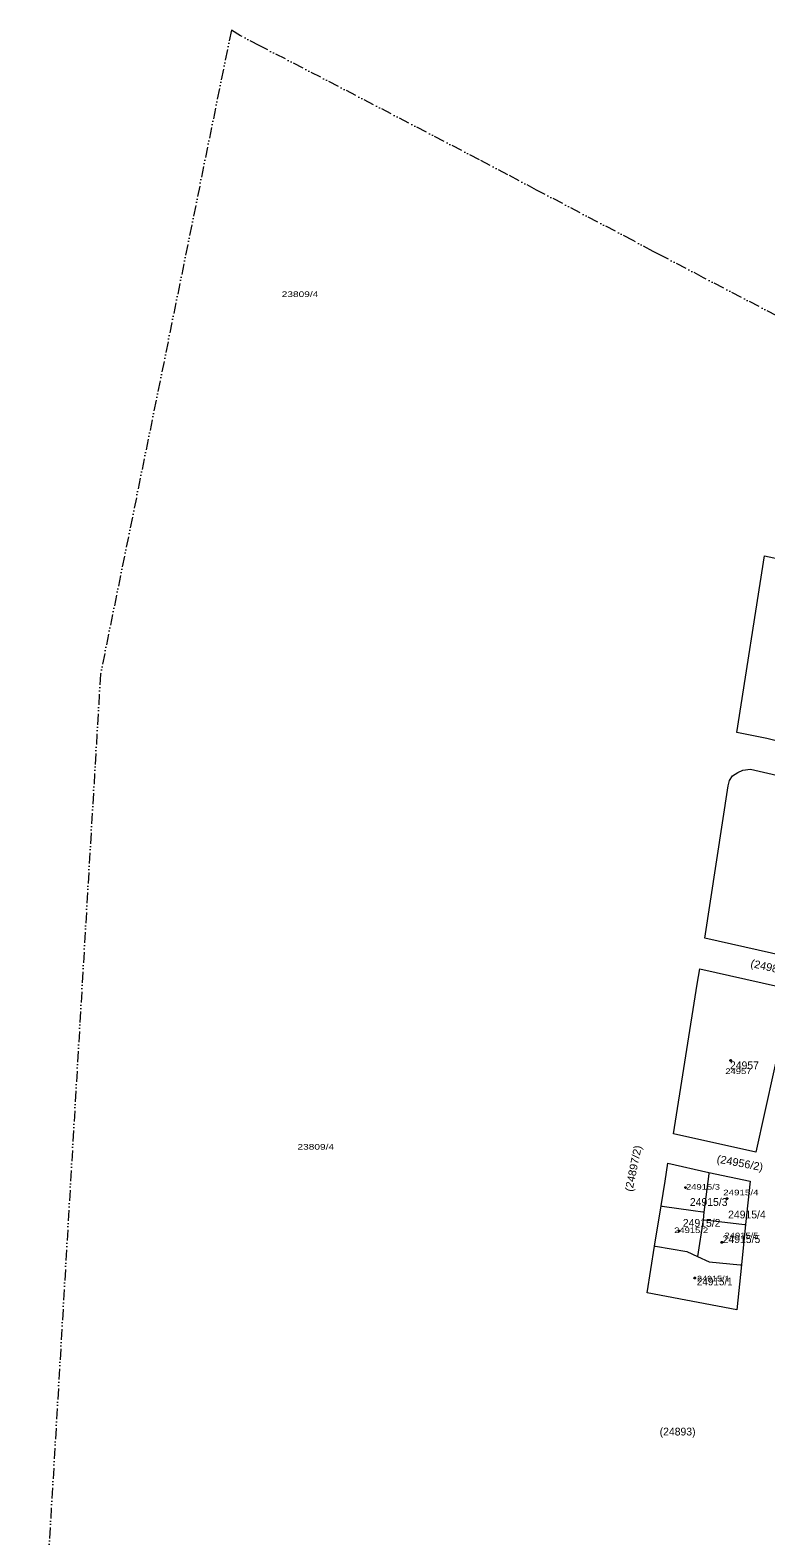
# Model space of a CAD drawing. Extents: x 649608 to 651081, y 237980 to 241202.
# Drawn here: x 649608 to 649949, y 240505 to 241202 of the extents above; entities that cross this region are included whole.
import ezdxf

# ---------------------------------------------------------------- set-up
doc = ezdxf.new("R2010")
doc.units = 0
doc.header["$PDMODE"] = 32
doc.header["$PDSIZE"] = 0.5
doc.linetypes.add('DASH_DOUBLE_DOT', pattern=[9.2, 5, -1.2, 0.3, -1.2, 0.3, -1.2])
for name, color, linetype in [('19', 7, 'Continuous'), ('20', 7, 'Continuous'), ('6', 7, 'Continuous')]:
    doc.layers.add(name, color=color, linetype=linetype)
for name, color, linetype, lineweight in [('3', 7, 'Continuous', 13), ('5', 7, 'Continuous', 13), ('52', 7, 'DASH_DOUBLE_DOT', 13)]:
    doc.layers.add(name, color=color, linetype=linetype, lineweight=lineweight)

msp = doc.modelspace()

# ---------------------------------------------------------------- linework, layer by layer
at = {"layer": '3'}
msp.add_line((649903.384, 240678.051), (649922.472, 240673.617), dxfattribs=at)
for points in [[(649984.472, 240865.644), (649949.238, 240874.49), (649935.422, 240877.247), (649948.175, 240959.032), (650002.431, 240947.466)], [(649963.751, 240772.414), (649920.651, 240782.136), (649931.296, 240852.609), (649931.915, 240855.114), (649933.387, 240857.24), (649935.862, 240858.812), (649935.887, 240858.811), (649938.131, 240859.789), (649941.756, 240860.26), (649981.062, 240851.161), (649964.785, 240776.903)], [(649918.324, 240767.869), (649960.797, 240758.3), (649944.236, 240683.1), (649906.134, 240691.619), (649917.099, 240760.848)]]:
    msp.add_lwpolyline(points, close=True, dxfattribs=at)
for points in [[(649937.476, 240630.882), (649935.436, 240610.08), (649893.884, 240617.978), (649897.237, 240639.641), (649900.319, 240658.225), (649902.151, 240669.688), (649903.384, 240678.051)], [(649922.472, 240673.617), (649941.563, 240669.655), (649939.452, 240649.599), (649937.476, 240630.882)]]:
    msp.add_lwpolyline(points, dxfattribs=at)
at = {"layer": '5'}
for points in [[(649922.472, 240673.617), (649922.409, 240673.117), (649920.602, 240658.788), (649920.174, 240655.35), (649919.797, 240651.814), (649917.227, 240634.846)], [(649900.319, 240658.225), (649900.819, 240658.15), (649915.161, 240656.003), (649919.674, 240655.415), (649920.174, 240655.35)], [(649919.797, 240651.814), (649920.297, 240651.764), (649924.606, 240651.333), (649938.952, 240649.657), (649939.452, 240649.599)], [(649897.237, 240639.641), (649897.737, 240639.558), (649912.265, 240637.141), (649917.227, 240634.846)], [(649917.227, 240634.846), (649922.592, 240632.383), (649936.976, 240630.932), (649937.476, 240630.882)]]:
    msp.add_lwpolyline(points, dxfattribs=at)
at = {"layer": '52'}
for points in [[(649701.481, 241202.319), (649640.936, 240904.262), (649608.393, 240352.424), (649614.771, 240009.578), (649631.5, 239894.49), (649662.347, 239679.564), (649715.192, 239448.546), (649776.71, 239295.263), (649918.979, 238940.568), (649995.713, 238777.318), (650020.382, 238724.355), (650126.69, 238550.145), (650295.37, 238327.169), (650466.153, 238100.489), (650557.889, 237992.529), (650568.158, 237979.989)], [(650055.166, 241019.937), (650013.492, 241039.791), (650004.23, 241044.161), (649999.823, 241046.243), (649991.118, 241050.924), (649986.568, 241053.226), (649920.012, 241087.763), (649901.022, 241097.763), (649896.603, 241099.955), (649887.398, 241104.972), (649842.73, 241128.344), (649829.448, 241135.382), (649816.32, 241142.347), (649714.629, 241195.131), (649705.792, 241199.756), (649701.481, 241202.319)]]:
    msp.add_lwpolyline(points, dxfattribs=at)
at = {"layer": '6'}
for p in [(649932.534, 240725.484), (649911.637, 240666.7), (649930.837, 240661.608), (649908.689, 240646.535), (649928.396, 240641.348), (649915.917, 240624.86)]:
    msp.add_point(p, dxfattribs=at)

# ---------------------------------------------------------------- texts
at = {"layer": '19', "width": 1.05}
for s, rotation, p in [('(24987)', 347.356, (649941.457, 240768.856)), ('(24897/2)', 78.276, (649887.021, 240664.589)), ('(24956/2)', 349.387, (649925.876, 240678.303))]:
    msp.add_text(s, height=3.6, rotation=rotation, dxfattribs=at).set_placement(p)
at = {"layer": '19'}
for s, p in [('24957', (649932.216, 240721.477)), ('24915/3', (649913.651, 240658.192)), ('24915/4', (649931.353, 240652.423)), ('24915/2', (649910.4, 240648.543)), ('24915/5', (649928.825, 240641.028)), ('(24893)', (649899.683, 240551.96))]:
    msp.add_text(s, height=3.6, dxfattribs=at).set_placement(p)
at = {"layer": '19', "width": 0.95}
msp.add_text('24915/1', height=3.6, dxfattribs=at).set_placement((649916.903, 240621.419))
at = {"layer": '20'}
for s, width, p in [('23809/4', 1.35, (649724.773, 241078.82)), ('24957', 1.25, (649930.066, 240719.233)), ('23809/4', 1.35, (649732.063, 240684.241)), ('24915/3', 1.25, (649911.873, 240665.707)), ('24915/4', 1.3, (649929.061, 240663.085)), ('24915/2', 1.25, (649906.393, 240645.635)), ('24915/5', 1.25, (649929.692, 240643.199)), ('24915/1', 1.2, (649916.967, 240623.248))]:
    msp.add_text(s, height=2.6, dxfattribs=dict(at, width=width)).set_placement(p)

doc.saveas('drawing.dxf')
